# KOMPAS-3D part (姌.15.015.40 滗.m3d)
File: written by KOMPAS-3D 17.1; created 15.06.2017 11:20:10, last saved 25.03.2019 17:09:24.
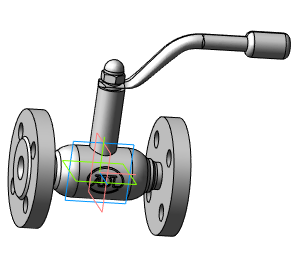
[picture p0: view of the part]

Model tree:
1. Операция без истории:2  (labels: Сталь 20  ГОСТ 1050-88)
